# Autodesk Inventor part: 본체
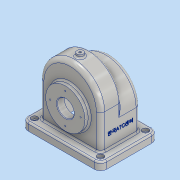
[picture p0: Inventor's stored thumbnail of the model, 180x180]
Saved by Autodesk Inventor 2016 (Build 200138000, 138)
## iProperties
Created: 2017-11
Part Number: 본체
Material: 알루미늄 6061
Document SubType Name: Modeling
Designer: 605-12
Density: 2.7 g/cm^3
Appearance: 알루미늄 - 평지
Mass: 1087.67 g
Surface Area: 1191.13 cm^2
Volume: 402.841 cm^3
Author: 605-12
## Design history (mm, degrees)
sketch "스케치1"
  geometry: L1 (-58, 0)-(58, 0); L2 (58, 0)-(58, 80); L3 (-58, 80)-(-58, 0); A1 r 58 centre (0, 80) between (58, 80) and (-58, 80); 2 further points
  constraints: 6 end point, 2 point on circle, 2 tangent, 1 centre point, 1 coincident, 1 horizontal, 1 midpoint, 1 perpendicular, 1 vertical, 1 vertical alignment
  dimensions: "d0" = 80 distance from line of A1.centre L1; "d1" = 58 radius of A1
extrude "돌출1" new body sketch "스케치1" distance "d2" = 38; taper "d3" = 0 deg
sketch "스케치2"
  geometry: L1 (-58, 0)-(-58, 57); L2 (58, 57)-(58, 0); L3 (58, 0)-(-58, 0); A1 r 58 centre (0, 57) between (58, 57) and (-58, 57); 2 further points
  constraints: 6 end point, 2 point on circle, 2 tangent, 2 vertical, 1 centre point, 1 coincident, 1 midpoint, 1 perpendicular, 1 vertical alignment
  dimensions: "d4" = 57 distance of point (0, 0) A1.centre; "d5" = 58 radius of A1
extrude "돌출2" join sketch "스케치2" distance "d6" = 38; taper "d7" = 0 deg
feature "쉘1" dims "d8" = 5
sketch "스케치3"
  geometry: L1 (-17, -93)-(133, -93); L2 (133, -93)-(133, 17); L3 (133, 17)-(-17, 17); L4 (-17, 17)-(-17, -93); L5 (0, -38)-(0, -76) reference; L6 (0, -76)-(116, -76) reference; L7 (116, -38)-(116, -76) reference; L8 (116, -38)-(116, 0) reference; L9 (116, 0)-(0, 0) reference; L10 (0, -38)-(0, 0) reference; 3 further points
  constraints: 8 end point, 2 midpoint, 2 parallel, 1 horizontal, 1 horizontal alignment, 1 perpendicular, 1 vertical alignment
  dimensions: "d9" = 110 distance of L3.end L1.start; "d10" = 150 distance of L2.end L3.end
extrude "돌출3" join sketch "스케치3" distance "d11" = 15; taper "d12" = 0 deg
fillet "모깎기1" dims "d13" = 12
fillet "모깎기2" dims "d14" = 3
hole "구멍1" diameter "d17" = 5; stored, may be unused: countersink angle "d21" = 90 deg, drill point angle "d23" = 118 deg; dims "d15" = 10, "d16" = 10, "d18" = 6, "d19" = 12, "d20" = 5, "d22" = 8
hole "구멍2" diameter "d26" = 5; stored, may be unused: countersink angle "d30" = 90 deg, drill point angle "d32" = 118 deg; dims "d24" = 10, "d25" = 10, "d27" = 6, "d28" = 12, "d29" = 5, "d31" = 8
hole "구멍3" diameter "d35" = 5; stored, may be unused: countersink angle "d39" = 90 deg, drill point angle "d41" = 118 deg; dims "d33" = 10, "d34" = 10, "d36" = 6, "d37" = 12, "d38" = 5, "d40" = 8
hole "구멍4" diameter "d44" = 5; stored, may be unused: countersink angle "d48" = 90 deg, drill point angle "d50" = 118 deg; dims "d42" = 10, "d43" = 10, "d45" = 6, "d46" = 12, "d47" = 5, "d49" = 8
sketch "스케치4"
  geometry: C1 r 37.5 at (0, 65); 1 further point
  constraints: 1 centre point, 1 vertical alignment
  dimensions: "d51" = 75 diameter of C1; "d52" = 65 distance of point (0, 0) C1.centre
extrude "돌출4" join sketch "스케치4" distance "d53" = 9; taper "d54" = 0 deg
sketch "스케치5"
  geometry: C1 r 31 at (0, 65); 1 further point
  constraints: 1 centre point, 1 vertical alignment
  dimensions: "d55" = 62 diameter of C1; "d56" = 65 distance of point (0, 0) C1.centre
extrude "돌출5" join sketch "스케치5" distance "d57" = 10; taper "d58" = 0 deg
node "작업 평면1"
sketch "스케치6"
  geometry: L1 (58, 38)-(-58, 38) reference; C1 r 6 at (0, 19); 1 further point
  constraints: 1 centre point, 1 vertical alignment
  dimensions: "d60" = 19 distance from line of C1.centre L1; "d61" = 12 diameter of C1
extrude "돌출6" join sketch "스케치6" distance "d62" = 6; taper "d63" = 0 deg
extrude "돌출7" join sketch "스케치6" distance "d98" = 3; taper "d99" = 0 deg
hole "구멍5" diameter "d66" = 32; stored, may be unused: countersink angle "d70" = 90 deg, drill point angle "d72" = 118 deg; dims "d64" = 10, "d65" = 10, "d67" = 6, "d68" = 12, "d69" = 5, "d71" = 8
sketch "스케치7"
  geometry: C1 r 37.5 at (0, 0) reference; 2 further points
  constraints: 1 vertical alignment
  dimensions: "d73" = 29 distance of C1.centre point (0, 29)
hole "구멍6" sketch "스케치7" at (0, 29) diameter "d74" = 2.459; stored, may be unused: countersink angle "d78" = 90 deg, drill point angle "d80" = 118 deg; dims "d75" = 6, "d76" = 12, "d77" = 5, "d79" = 8
sketch "스케치8"
  geometry: C1 r 31 at (0, 0) reference; 2 further points
  constraints: 1 vertical alignment
  dimensions: "d84" = 26 distance of C1.centre point (0, 26)
hole "구멍7" sketch "스케치8" at (0, 26) diameter "d85" = 2.459; stored, may be unused: countersink angle "d89" = 90 deg, drill point angle "d91" = 118 deg; dims "d86" = 6, "d87" = 12, "d88" = 5, "d90" = 8
fillet "모깎기4" dims "d96" = 8
fillet "모깎기5" dims "d97" = 3
fillet "모깎기6" dims "d100" = 3
hole "구멍8" diameter "d103" = 4.134; stored, may be unused: countersink angle "d107" = 90 deg, drill point angle "d109" = 118 deg; dims "d104" = 15, "d105" = 12, "d106" = 5, "d108" = 14.2, "d117" = 10, "d118" = 10
chamfer "모따기1" distance "d110" = 1; stored, may be unused: second distance "d111" = 2, angle "d112" = 45 deg
fillet "모깎기7" dims "d116" = 3
fillet "모깎기8" dims "d119" = 3
fillet "모깎기9" dims "d120" = 3
sketch "스케치10"
  geometry: 2 further points
  constraints: 1 vertical alignment, 1 other
  dimensions: "d121" = 40 distance of point (30, -18) point (30, 22)
feature "엠보싱2" sketch "스케치10" dims "d0" = 80, "d1" = 58, "d122" = 0.5, "d123" = 0
node "솔리드1"
pattern_circular "원형 패턴1" dims angle "d82" = 360 deg
pattern_circular "원형 패턴2" dims angle "d93" = 360 deg
other parameters: "d59" = 138
